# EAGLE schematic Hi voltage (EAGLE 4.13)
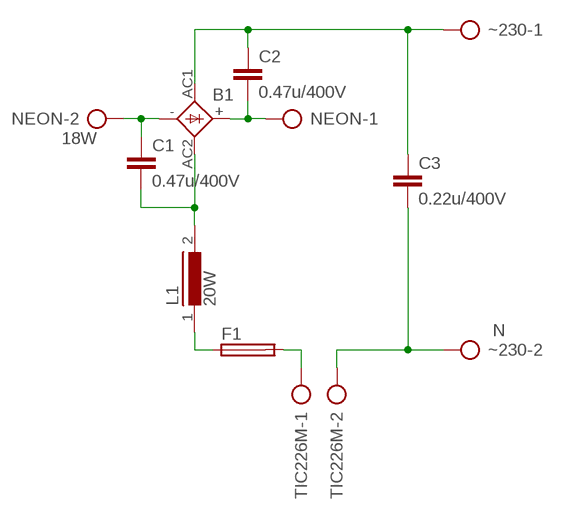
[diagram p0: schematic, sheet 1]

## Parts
B1  FB32  [FB32]
C1  0.47u/400V  C-EU275-113X316  [C275-113X316]
C2  0.47u/400V  C-EU275-113X316  [C275-113X316]
C3  0.22u/400V  C-EU275-113X316  [C275-113X316]
F1  GSH15  [GSH15]
L1  20W  B825-35  [B825-35]
NEON  18W  AK300/2  [AK300/2]
TIC226M  AK300/2  [AK300/2]
~230  N  AK300/2  [AK300/2]

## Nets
N$1: B1.- C1.1 NEON.2
N$2: B1.+ C2.2 NEON.1
N$3: B1.AC1 C2.1 C3.1 ~230.1
N$4: B1.AC2 C1.2 L1.2
N$5: F1.2 TIC226M.1
N$6: C3.2 TIC226M.2 ~230.2
N$7: F1.1 L1.1

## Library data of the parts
B1 = rectifier:FB32: FAGOR RECTIFIER grid 1 x 10,2 x 7,5 mm
C1-C3 = rcl:C-EU: CAPACITOR, European symbol
F1 = fuse:GSH15: FUSE HOLDER
L1 = inductors:B825-35: INDUCTOR
NEON TIC226M ~230 = con-ptr500:AK300/2: CONNECTOR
